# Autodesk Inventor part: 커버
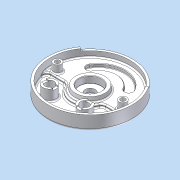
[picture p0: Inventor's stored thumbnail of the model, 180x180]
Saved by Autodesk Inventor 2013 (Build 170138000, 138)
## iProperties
Company: 한국ATC센터
Created: 2015-04
Part Number: 커버
Document SubType Name: Modeling
Designer: KYOUNG IL JANG
Density: 1 g/cm^3
Material: 알루미늄 6061
Mass: 394.015 g
Surface Area: 1019.6 cm^2
Volume: 394.015 cm^3
Author: KYOUNG IL JANG
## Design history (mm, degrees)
sketch "스케치1"
  geometry: L1 (-59, -19)-(-59, 19); L2 (59, 19)-(59, -19); L3 (-41, 19)-(-41, -19); L4 (41, -19)-(41, 19); L5 (38.527, 33.023)-(55.442, 39.179); L6 (-38.527, 33.023)-(-55.442, 39.179); C1 r 90 at (0, 0); C2 r 95 at (0, 0); A1 r 59 centre (0, 19) between (59, 19) and (-59, 19); A2 r 59 centre (0, -19) between (-59, -19) and (59, -19); A3 r 41 centre (0, -19) between (-41, -19) and (41, -19); A4 r 41 centre (0, 19) between (41, 19) and (-41, 19); 2 further points
  constraints: 12 end point, 12 point on circle, 6 centre point, 4 tangent, 2 parallel, 2 point on line, 1 coincident, 1 horizontal alignment, 1 midpoint, 1 vertical, 1 vertical alignment, 3 other
  dimensions: "d2" = 180 diameter of C1; "d3" = 156 dimension on A2 A1; "d4" = 118 distance between parallel lines of L2 L1; "d5" = 18 distance between parallel lines of L2 L4; "d8" = 190 diameter of C2; "d120" = 140 deg angle of L6 L5; "d121" = 110 deg dimension on A1.centre point (0, 0) L5.end
extrude "돌출1" new body sketch "스케치1" distance "d6" = 14; taper "d7" = 0 deg
extrude "돌출2" join sketch "스케치1" distance "d9" = 13; taper "d10" = 0 deg
extrude "돌출3" cut sketch "스케치1" distance "d11" = 7; taper "d12" = 0 deg
sketch "스케치2"
  geometry: C1 r 11.5 at (0, 0); 1 further point
  constraints: 1 centre point, 1 coincident
  dimensions: "d13" = 23 diameter of C1
extrude "돌출4" cut sketch "스케치2" stored distance "d14" = 7; taper "d15" = 0 deg
fillet "모깎기1"
fillet "모깎기2"
sketch "스케치3"
  geometry: L1 (-73.724, 51.622)-(-77.819, 54.49); L2 (73.724, 51.622)-(77.819, 54.49); L3 (0, 0)-(0, -90); A1 r 95 centre (0, 0) between (-77.819, 54.49) and (77.819, 54.49) reference; A2 r 90 centre (0, 0) between (-73.724, 51.622) and (73.724, 51.622) reference; 1 further point
  constraints: 6 end point, 5 point on circle, 1 point on line, 1 vertical, 1 other
  dimensions: "d16" = 250 deg dimension on L2 L1
extrude "돌출5" join sketch "스케치3" distance "d17" = 5; taper "d18" = 0 deg
hole "구멍1" diameter "d21" = 50; stored, may be unused: countersink angle "d25" = 90 deg, drill point angle "d27" = 0 deg; dims "d19" = 10, "d20" = 10, "d22" = 6, "d23" = 4, "d24" = 2, "d26" = 5
fillet "모깎기3" dims "d28" = 0.3
fillet "모깎기5" dims "d30" = 3
sketch "스케치4"
  geometry: C1 r 35 at (0, 0); C2 r 25 at (0, 0); 1 further point
  constraints: 2 centre point, 1 coincident
  dimensions: "d32" = 70 diameter of C1 (derived); "d36" = 10 radial gap between concentric circles of C1 C2
extrude "돌출6" join sketch "스케치4" distance "d33" = 10; taper "d34" = 0 deg
feature "면 기울기2" dims angle "d37" = 10 deg
chamfer "모따기1" distance "d39" = 1; stored, may be unused: second distance "d40" = 2, angle "d41" = 45 deg
fillet "모깎기7" dims "d42" = 5
sketch "스케치5"
  geometry: L1 (-40.249, -12)-(-89.196, -12); L2 (40.249, -12)-(89.196, -12); A1 r 90 centre (0, 0) between (-89.196, -12) and (89.196, -12) reference; A2 r 42 centre (0, 0) between (-40.249, -12) and (40.249, -12); 1 further point
  constraints: 4 end point, 4 point on circle, 1 centre point, 1 collinear, 1 horizontal, 1 point on line
  dimensions: "d43" = 48 radial gap between concentric circles of A1 A2; "d44" = 12 distance from line of point (0, 0) L1
extrude "돌출7" cut sketch "스케치5" stored distance "d45" = 10; taper "d46" = 0 deg
fillet "모깎기8" dims "d47" = 10
chamfer "모따기2" distance "d49" = 1; stored, may be unused: second distance "d50" = 2, angle "d51" = 45 deg
sketch "스케치7"
  geometry: L1 (36.062, 36.062)-(50.912, 50.912); L2 (-36.062, 36.062)-(-50.912, 50.912); A1 r 72 centre (0, 0) between (50.912, 50.912) and (-50.912, 50.912); A2 r 51 centre (0, 0) between (36.062, 36.062) and (-36.062, 36.062); 1 further point
  constraints: 8 point on circle, 4 end point, 2 centre point, 2 point on line, 1 coincident, 1 horizontal alignment
  dimensions: "d54" = 72 radius of A1; "d55" = 21 radial gap between concentric circles of A1 A2; "d56" = 90 deg angle of L2 L1
extrude "돌출8" join sketch "스케치7" distance "d57" = 5; taper "d58" = 0 deg
fillet "모깎기10" dims "d59" = 5
fillet "모깎기11" dims "d60" = 5
fillet "모깎기12" dims "d61" = 3
sketch "스케치6"
  geometry: C1 r 68 at (0, 0); 1 further point
  constraints: 1 centre point, 1 other
  dimensions: "d119" = 136 diameter of C1
feature "엠보싱1" sketch "스케치6" dims "d62" = 0.5, "d63" = 0
sketch "스케치8"
  geometry: C1 r 9 at (74, 0); C2 r 9 at (-74, 0); A1 r 74 centre (0, 0) between (74, 0) and (-74, 0); 1 further point
  constraints: 3 centre point, 2 horizontal alignment, 2 point on circle, 1 coincident, 1 equal radius
  dimensions: "d64" = 18 diameter of C1; "d65" = 148 diameter of A1
extrude "돌출9" join sketch "스케치8" stored distance "d66" = 5; taper "d67" = 0 deg
sketch "스케치11"
  geometry: C1 r 15 at (40, -52); C2 r 15 at (-40, -52); 1 further point
  constraints: 2 centre point, 1 equal radius, 1 horizontal alignment
  dimensions: "d83" = 52 vertical distance of point (0, 0) C1.centre; "d84" = 80 distance of C2.centre C1.centre; "d85" = 40 horizontal distance of point (0, 0) C1.centre (= 0.5 x d84); "d86" = 30 diameter of C1
extrude "돌출10" join sketch "스케치11" stored distance "d87" = 5; taper "d88" = 0 deg
node "구멍3"
node "구멍5"
hole "구멍6" diameter "d93" = 20; stored, may be unused: countersink angle "d97" = 90 deg, drill point angle "d99" = 118 deg; dims "d91" = 10, "d92" = 10, "d94" = 6, "d95" = 4, "d96" = 2, "d98" = 8
hole "구멍7" diameter "d102" = 20; stored, may be unused: countersink angle "d106" = 90 deg, drill point angle "d108" = 118 deg; dims "d100" = 10, "d101" = 10, "d103" = 6, "d104" = 4, "d105" = 2, "d107" = 8
sketch "스케치13"
  geometry: L1 (6, -13.748)-(6, -8); L2 (6, 8)-(6, 13.748); L3 (-6, -13.748)-(-6, -8); L4 (-6, 8)-(-6, 13.748); L5 (-66.252, -6)-(-72, -6); L6 (-88, -6)-(-93.748, -6); L7 (-66.252, 6)-(-72, 6); L8 (-88, 6)-(-93.748, 6); A1 r 15 centre (0, 0) between (6, -13.748) and (6, 13.748) reference; A2 r 10 centre (0, 0) between (6, -8) and (6, 8) reference; A3 r 15 centre (-80, 0) between (-66.252, -6) and (-93.748, -6) reference; A4 r 10 centre (-80, 0) between (-72, -6) and (-88, -6) reference; 1 further point
  constraints: 16 end point, 16 point on circle, 4 equal length, 3 collinear, 2 point on line, 1 perpendicular, 1 vertical
  dimensions: "d109" = 12 distance between parallel lines of L3 L1; "d110" = 6 distance from line of A1.centre L1 (= 0.5 x d109); "d111" = 12 distance between parallel lines of L7 L5; "d112" = 6 distance from line of A3.centre L5 (= 0.5 x d111)
extrude "돌출12" cut sketch "스케치13" distance "d113" = 3; taper "d114" = 0 deg
fillet "모깎기13" dims "d115" = 3
fillet "모깎기14" dims "d116" = 1
node "솔리드1"
sketch "스케치9"
  geometry: 1 further point
hole "구멍2" sketch "스케치9" diameter "d68" = 11; stored, may be unused: countersink angle "d72" = 90 deg, drill point angle "d74" = 0 deg; dims "d69" = 6, "d70" = 18, "d71" = 11, "d73" = 8
sketch "스케치10"
  geometry: 1 further point
hole "구멍4" sketch "스케치10" diameter "d75" = 11; stored, may be unused: countersink angle "d79" = 90 deg, drill point angle "d81" = 0 deg; dims "d76" = 6, "d77" = 18, "d78" = 11, "d80" = 8
